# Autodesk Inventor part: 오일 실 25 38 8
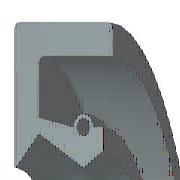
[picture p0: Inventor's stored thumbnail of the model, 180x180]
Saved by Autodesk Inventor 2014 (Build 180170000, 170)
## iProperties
Created: 2012-02
Part Number: 오일 실 25 38 8
Material: 고무
Description: 오일-실
Document SubType Name: Modeling
Standard: KS B 2804
Designer: mduedu
Standards Organization: KS
Language: ko-KR
Size Designation: D - 25 38 8
Categories: <MemberInstance><Categories><Category DisplayName="샤프트 부품" InternalName="7f7aeb1f-a693-4053-b835-cee3144e0d98" Mnemonic="SHFT"><Category DisplayName="실링" Intern
Density: 0.93 g/cm^3
Appearance: 고무 - 검은색 - 버전 1.1
Mass: 2.72583 g
Surface Area: 38.9868 cm^2
Volume: 2.931 cm^3
IsCustomPart: 1
Author: mduedu
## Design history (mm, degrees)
revolve "본체" stored, may be unused: angle "d17" = 90 deg
revolve "스프링1" stored, may be unused: angle "d18" = 90 deg
body "Solid1"
sketch "스케치1"
  geometry: L1 (0, 19)-(8, 19); L2 (8, 17.25)-(1.75, 17.25); L3 (1.75, 14.25)-(4.9, 12.5); L4 (4.9, 12.5)-(0, 12.5); L5 (0, 0)-(9.586, 0) reference; L6 (4.9, 12.5)-(6.3, 13.375); L7 (0, 18)-(0, -3) reference; L8 (-1.941, 0)-(11.507, 0) reference; L9 (4.2, 14.6)-(1.75, 15.21); L10 (1.75, 15.21)-(1.75, 17.25); L11 (0, 19)-(0, 12.588); L12 (4.9, 12.5)-(0, 12.5); L13 (1.75, 14.25)-(0.152, 12.528); L14 (8, 19)-(8, 17.25); L15 (5.6, 14.6)-(6.3, 14.6); L16 (6.3, 14.6)-(6.3, 13.375); C1 r 0.455 at (4.9, 14.6); A1 r 0.7 centre (4.9, 14.6) between (5.6, 14.6) and (4.2, 14.6); A2 r 0.088 centre (0.087, 12.588) between (0, 12.588) and (0.152, 12.528); 1 further point
  constraints: 28 end point, 5 horizontal alignment, 5 point on line, 4 point on circle, 4 vertical alignment, 3 centre point, 3 tangent, 2 collinear, 2 horizontal, 2 perpendicular, 1 coincident, 1 parallel
  dimensions: "d0" = 38 diameter of L1 L5 (= SD2); "d1" = 1.75 distance of L1.end L2.start (= SD); "d2" = 0.91 diameter of C1 (= SPDI); "d3" = 1.4 diameter of A1 (= SPDA); "d4" = 25 diameter of L3.end L5 (= NND); "d5" = 28.5 diameter of L3.start L5 (= TKDM); "d7" = 30.42 diameter of L9.end L5 (= TKDM + 0.24 x SWDT); "d8" = 1.75 distance between parallel lines of L11 L10 (= SD); "d9" = 4.9 distance from line of L11 C1.centre (= SPDST); "d10" = 29.2 diameter of C1.centre L5 (= HLDM); "d11" = 0.0875 radius of A2 (= 0.25 x LAB); "d12" = 6.3 distance between parallel lines of L11 L16 (= SDI); "d13" = 26.75 diameter of L6.end L5 (= ABDM); "d14" = 8 distance from line of L11 L1.end (= SWDT)
fillet "모깎기1" dims "d6" = 0.3 (= RR)
other parameters: "SD2" = 38 [user parameter; used in 1 equation term], "SWDT" = 8 [user parameter; used in 2 equation terms], "RR" = 0.3 [user parameter; used in 1 equation term], "SD" = 1.75 [user parameter; used in 2 equation terms], "NND" = 25 [user parameter; used in 1 equation term], "SPDA" = 1.4 [user parameter; used in 1 equation term], "SPDI" = 0.91 [user parameter; used in 1 equation term], "TKDM" = 28.5 [user parameter; used in 2 equation terms], "HLDM" = 29.2 [user parameter; used in 1 equation term], "ABDM" = 26.75 [user parameter; used in 1 equation term], "SDI" = 6.3 [user parameter; used in 1 equation term], "SPDST" = 4.9 [user parameter; used in 1 equation term], "LAB" = 0.35 [user parameter; used in 1 equation term], "d15" = 0, "d16" = 0, "d19" = 0
